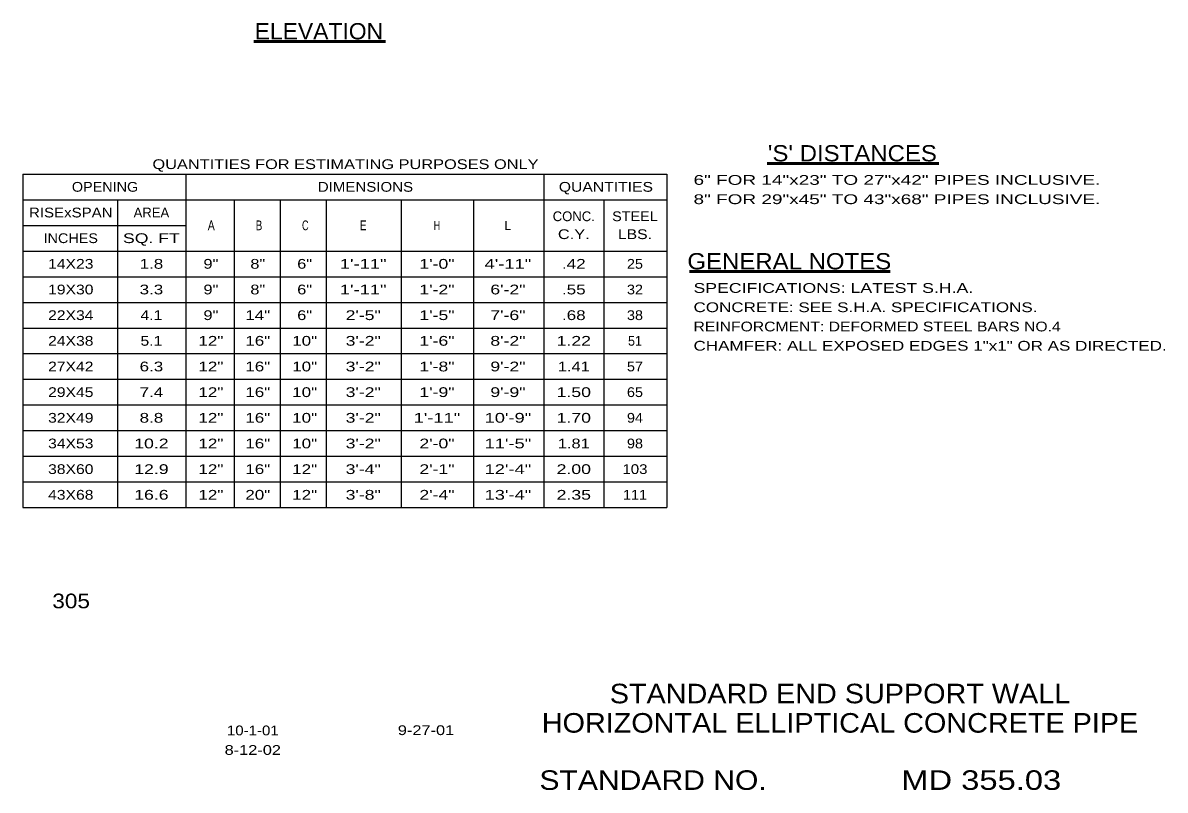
# Model space of a CAD drawing. Extents: x 394.95 to 401.96, y -76.51 to -66.78.
# Drawn here: x 394.95 to 401.96, y -76.51 to -71.8 of the extents above; entities that cross this region are included whole.
import ezdxf
from ezdxf.enums import TextEntityAlignment as Align

# ---------------------------------------------------------------- set-up
doc = ezdxf.new("R2010")
doc.units = 0
doc.header["$LTSCALE"] = 0.024
doc.layers.add('12', color=7, linetype='Continuous')
doc.layers.add('13', color=7, linetype='Continuous', lineweight=25)

msp = doc.modelspace()

# ---------------------------------------------------------------- linework, layer by layer
at = {"layer": '13', "lineweight": 53}
for p, q in [((396.36657, -71.91373), (397.17395, -71.91373)), ((399.51462, -72.6625), (400.56807, -72.6625)), ((399.03942, -73.32557), (400.26954, -73.32557))]:
    msp.add_line(p, q, dxfattribs=at)
at = {"layer": '13'}
for p, q in [((394.94906, -72.72767), (398.89891, -72.72767)), ((394.94906, -72.72767), (394.94906, -74.77517)), ((395.94908, -72.72767), (395.94908, -74.77517)), ((398.14401, -72.72767), (398.14401, -74.77517)), ((398.89891, -72.72767), (398.89891, -74.77517)), ((394.94906, -72.88517), (398.89891, -72.88517)), ((395.52868, -72.88517), (395.52868, -74.77517)), ((396.24452, -72.88517), (396.24452, -74.77517)), ((396.52746, -72.88517), (396.52746, -74.77517)), ((396.8104, -72.88517), (396.8104, -74.77517)), ((397.26946, -72.88517), (397.26946, -74.77517)), ((397.71289, -72.88517), (397.71289, -74.77517)), ((398.51226, -72.88517), (398.51226, -74.77517)), ((394.94906, -73.04267), (395.94908, -73.04267)), ((394.94906, -73.20017), (398.89891, -73.20017)), ((394.94906, -73.35767), (398.89891, -73.35767)), ((394.94906, -73.51517), (398.89891, -73.51517)), ((394.94906, -73.67267), (398.89891, -73.67267)), ((394.94906, -73.83017), (398.89891, -73.83017)), ((394.94906, -73.98767), (398.89891, -73.98767)), ((394.94906, -74.14517), (398.89891, -74.14517)), ((394.94906, -74.30267), (398.89891, -74.30267)), ((394.94906, -74.46017), (398.89891, -74.46017)), ((394.94906, -74.61767), (398.89891, -74.61767)), ((394.94906, -74.77517), (398.89891, -74.77517))]:
    msp.add_line(p, q, dxfattribs=at)

# ---------------------------------------------------------------- texts
at = {"layer": '12', "width": 1.05}
msp.add_text('ELEVATION', height=0.1, dxfattribs=at).set_placement((396.76496, -71.90122), align=Align.CENTER)
at = {"layer": '13'}
for s, height, width, p in [("'S' DISTANCES", 0.1, 1.1, (400.03748, -72.64998)), ('QUANTITIES FOR ESTIMATING PURPOSES ONLY', 0.06, 1.25, (396.92819, -72.69721)), ('OPENING', 0.06, 1.1, (395.45328, -72.83641)), ('DIMENSIONS', 0.06, 1.15, (397.05075, -72.83641)), ('QUANTITIES', 0.06, 1.2, (398.52566, -72.83641)), ('RISExSPAN', 0.06, 1.15, (395.24308, -72.99391)), ('A', 0.06, 0.8, (396.10485, -73.07267)), ('B', 0.06, 0.75, (396.39794, -73.07267)), ('C', 0.06, 0.7, (396.68168, -73.07267)), ('E', 0.06, 0.75, (397.03682, -73.07267)), ('STEEL', 0.06, 1.1, (398.70382, -73.01693)), ('H', 0.05528, 0.75, (397.489, -73.0703)), ('C.Y.', 0.06, 1.25, (398.32866, -73.12693)), ('LBS.', 0.06, 1.2, (398.70381, -73.12693)), ('INCHES', 0.06, 1.1, (395.24306, -73.15141)), ('SQ. FT', 0.06, 1.35, (395.73773, -73.15142)), ('GENERAL NOTES', 0.1, 1.1, (399.65063, -73.31305)), ('14X23', 0.06, 1.2, (395.24307, -73.30891)), ('1.8', 0.06, 1.3, (395.73773, -73.30892)), ('9"', 0.06, 1.25, (396.10261, -73.30892)), ('8"', 0.06, 1.25, (396.39024, -73.30892)), ('6"', 0.06, 1.25, (396.67789, -73.30892)), ('1\'-11"', 0.06, 1.4, (397.03683, -73.30892)), ('1\'-0"', 0.06, 1.35, (397.48933, -73.30892)), ('4\'-11"', 0.06, 1.4, (397.92453, -73.30892)), ('.42', 0.06, 1.3, (398.32866, -73.30892)), ('25', 0.06, 1.1, (398.70382, -73.30892)), ('19X30', 0.06, 1.2, (395.24307, -73.46641)), ('3.3', 0.06, 1.3, (395.73773, -73.46642)), ('9"', 0.06, 1.25, (396.10261, -73.46642)), ('8"', 0.06, 1.25, (396.39024, -73.46642)), ('6"', 0.06, 1.25, (396.67789, -73.46642)), ('1\'-11"', 0.06, 1.4, (397.03683, -73.46642)), ('1\'-2"', 0.06, 1.35, (397.48933, -73.46642)), ('6\'-2"', 0.06, 1.35, (397.92453, -73.46642)), ('.55', 0.06, 1.3, (398.32867, -73.46642)), ('32', 0.06, 1.1, (398.70382, -73.46642)), ('22X34', 0.06, 1.2, (395.24307, -73.62391)), ('4.1', 0.06, 1.2, (395.73774, -73.62392)), ('9"', 0.06, 1.25, (396.1026, -73.62392)), ('14"', 0.06, 1.3, (396.39024, -73.62392)), ('6"', 0.06, 1.25, (396.67789, -73.62392)), ('2\'-5"', 0.06, 1.35, (397.03683, -73.62392)), ('1\'-5"', 0.06, 1.35, (397.48933, -73.62392)), ('7\'-6"', 0.06, 1.35, (397.92453, -73.62392)), ('.68', 0.06, 1.3, (398.32866, -73.62392)), ('38', 0.06, 1.1, (398.70382, -73.62392)), ('24X38', 0.06, 1.2, (395.24307, -73.78141)), ('5.1', 0.06, 1.2, (395.73774, -73.78142)), ('12"', 0.06, 1.3, (396.1026, -73.78142)), ('16"', 0.06, 1.3, (396.39024, -73.78142)), ('10"', 0.06, 1.3, (396.67789, -73.78142)), ('3\'-2"', 0.06, 1.35, (397.03683, -73.78142)), ('1\'-6"', 0.06, 1.35, (397.48933, -73.78142)), ('8\'-2"', 0.06, 1.35, (397.92453, -73.78142)), ('1.22', 0.06, 1.35, (398.32866, -73.78142)), ('51', 0.06, 0.95, (398.70382, -73.78142)), ('27X42', 0.06, 1.2, (395.24307, -73.93891)), ('6.3', 0.06, 1.3, (395.73773, -73.93892)), ('12"', 0.06, 1.3, (396.1026, -73.93892)), ('16"', 0.06, 1.3, (396.39024, -73.93892)), ('10"', 0.06, 1.3, (396.67789, -73.93892)), ('3\'-2"', 0.06, 1.35, (397.03683, -73.93892)), ('1\'-8"', 0.06, 1.35, (397.48933, -73.93892)), ('9\'-2"', 0.06, 1.35, (397.92453, -73.93892)), ('1.41', 0.06, 1.25, (398.32867, -73.93892)), ('57', 0.06, 1.1, (398.70382, -73.93892)), ('29X45', 0.06, 1.2, (395.24306, -74.0964)), ('7.4', 0.06, 1.3, (395.73773, -74.09642)), ('12"', 0.06, 1.3, (396.1026, -74.09642)), ('16"', 0.06, 1.3, (396.39024, -74.09642)), ('10"', 0.06, 1.3, (396.67787, -74.09642)), ('3\'-2"', 0.06, 1.35, (397.03683, -74.09642)), ('1\'-9"', 0.06, 1.35, (397.48933, -74.09642)), ('9\'-9"', 0.06, 1.35, (397.92453, -74.09642)), ('1.50', 0.06, 1.35, (398.32866, -74.09642)), ('65', 0.06, 1.1, (398.70382, -74.09642)), ('32X49', 0.06, 1.2, (395.24305, -74.25389)), ('8.8', 0.06, 1.3, (395.73773, -74.25392)), ('12"', 0.06, 1.3, (396.1026, -74.25392)), ('16"', 0.06, 1.3, (396.39024, -74.25392)), ('10"', 0.06, 1.3, (396.67787, -74.25392)), ('3\'-2"', 0.06, 1.35, (397.03683, -74.25392)), ('1\'-11"', 0.06, 1.4, (397.48933, -74.25392)), ('10\'-9"', 0.06, 1.4, (397.92453, -74.25392)), ('1.70', 0.06, 1.35, (398.32866, -74.25392)), ('94', 0.06, 1.1, (398.70382, -74.25392)), ('34X53', 0.06, 1.2, (395.24304, -74.41137)), ('10.2', 0.06, 1.35, (395.73773, -74.41142)), ('12"', 0.06, 1.3, (396.1026, -74.41142)), ('16"', 0.06, 1.3, (396.39024, -74.41142)), ('10"', 0.06, 1.3, (396.67789, -74.41142)), ('3\'-2"', 0.06, 1.35, (397.03683, -74.41142)), ('2\'-0"', 0.06, 1.35, (397.48933, -74.41142)), ('11\'-5"', 0.06, 1.4, (397.92453, -74.41142)), ('1.81', 0.06, 1.25, (398.32867, -74.41142)), ('98', 0.06, 1.1, (398.70382, -74.41142)), ('38X60', 0.06, 1.2, (395.24303, -74.56886)), ('12.9', 0.06, 1.35, (395.73773, -74.56892)), ('12"', 0.06, 1.3, (396.1026, -74.56892)), ('16"', 0.06, 1.3, (396.39024, -74.56892)), ('12"', 0.06, 1.3, (396.67787, -74.56892)), ('3\'-4"', 0.06, 1.35, (397.03683, -74.56892)), ('2\'-1"', 0.06, 1.35, (397.48933, -74.56892)), ('12\'-4"', 0.06, 1.4, (397.92453, -74.56892)), ('2.00', 0.06, 1.35, (398.32866, -74.56892)), ('103', 0.06, 1.15, (398.70382, -74.56892)), ('43X68', 0.06, 1.2, (395.24302, -74.72636)), ('16.6', 0.06, 1.35, (395.73774, -74.72642)), ('12"', 0.06, 1.3, (396.1026, -74.72642)), ('20"', 0.06, 1.3, (396.39024, -74.72642)), ('12"', 0.06, 1.3, (396.67787, -74.72642)), ('3\'-8"', 0.06, 1.35, (397.03683, -74.72642)), ('2\'-4"', 0.06, 1.35, (397.48933, -74.72642)), ('13\'-4"', 0.06, 1.4, (397.92453, -74.72642)), ('2.35', 0.06, 1.35, (398.32866, -74.72642)), ('111', 0.06, 1.1, (398.70382, -74.72642)), ('STANDARD END SUPPORT WALL', 0.12, 1.1, (399.9617, -75.9761)), ('HORIZONTAL ELLIPTICAL CONCRETE PIPE', 0.12, 1.1, (399.9617, -76.1561)), ('10-1-01', 0.06, 1.15, (396.35963, -76.17247)), ('9-27-01', 0.06, 1.25, (397.42209, -76.17101)), ('8-12-02', 0.06, 1.25, (396.35964, -76.29247)), ('STANDARD NO.', 0.12, 1.15, (398.81495, -76.50744)), ('MD 355.03', 0.12, 1.25, (400.82799, -76.50743))]:
    msp.add_text(s, height=height, dxfattribs=dict(at, width=width)).set_placement(p, align=Align.CENTER)
for s, width, p in [('6" FOR 14"x23" TO 27"x42" PIPES INCLUSIVE.', 1.45, (399.06317, -72.79398)), ('8" FOR 29"x45" TO 43"x68" PIPES INCLUSIVE.', 1.45, (399.06317, -72.91223)), ('SPECIFICATIONS: LATEST S.H.A.', 1.35, (399.06317, -73.45705)), ('CONCRETE: SEE S.H.A. SPECIFICATIONS.', 1.3, (399.06317, -73.5753)), ('REINFORCMENT: DEFORMED STEEL BARS NO.4', 1.2, (399.06317, -73.69355)), ('CHAMFER: ALL EXPOSED EDGES 1"x1" OR AS DIRECTED.', 1.3, (399.06317, -73.8118))]:
    msp.add_text(s, height=0.06, dxfattribs=dict(at, width=width)).set_placement(p)
for s, height, p in [('AREA', 0.06, (395.73773, -72.99391)), ('CONC.', 0.06, (398.32866, -73.01693)), ('L', 0.05528, (397.9242, -73.0703))]:
    msp.add_text(s, height=height, dxfattribs=at).set_placement(p, align=Align.CENTER)
at = {"layer": '13', "width": 1.15}
msp.add_text('305', height=0.09, dxfattribs=at).set_placement((395.3607, -75.39289), align=Align.RIGHT)

doc.saveas('drawing.dxf')
